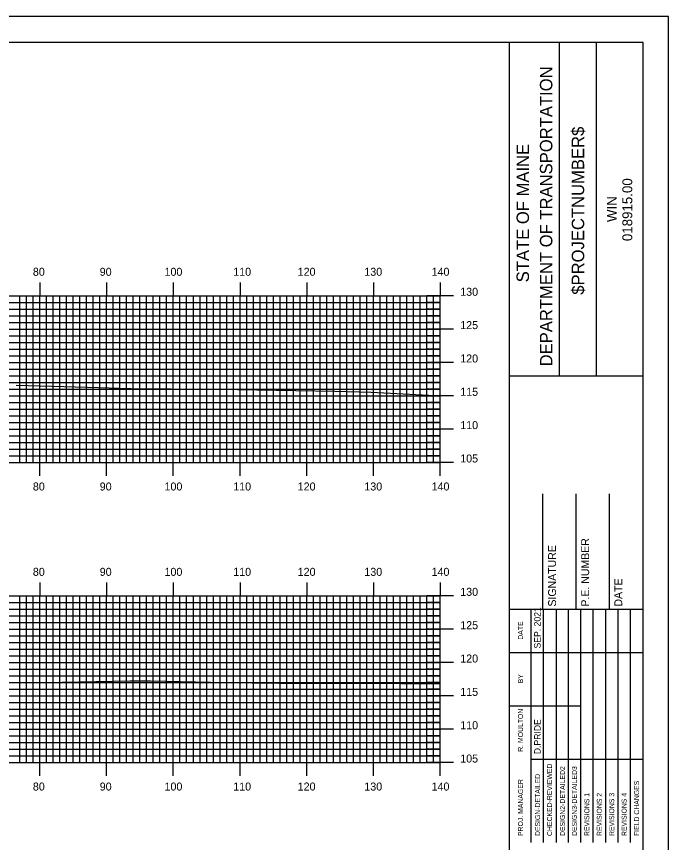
# Model space of a CAD drawing. Extents: x 844143 to 844486, y 363538 to 363758.
# Drawn here: x 844385 to 844482.7, y 363633.7 to 363757.6 of the extents above; entities that cross this region are included whole.
import ezdxf

# ---------------------------------------------------------------- set-up
doc = ezdxf.new("R2010")
doc.units = 0
for name, color, linetype in [('BORDER', 7, 'Continuous'), ('H_V ANNOTATION', 7, 'Continuous'), ('MAJOR', 7, 'Continuous'), ('MINOR', 7, 'Continuous'), ('PLOT BOUNDARY', 7, 'Continuous'), ('S_Roadway_Centerline', 7, 'Continuous')]:
    doc.layers.add(name, color=color, linetype=linetype)

msp = doc.modelspace()

# ---------------------------------------------------------------- linework, layer by layer
at = {"layer": 'BORDER'}
for p, q in [((844458.85, 363543.72), (844458.85, 363753.72)), ((844466.31, 363703.72), (844466.31, 363753.72)), ((844471.9, 363703.72), (844471.9, 363753.72)), ((844458.85, 363703.71), (844478.85, 363703.71)), ((844463.85, 363668.73), (844463.85, 363686.02)), ((844468.85, 363668.73), (844468.85, 363686.02)), ((844473.85, 363668.73), (844473.85, 363686.02)), ((844458.85, 363668.73), (844478.85, 363668.73))]:
    msp.add_line(p, q, dxfattribs=at)
msp.add_lwpolyline([(844158.85, 363543.72), (844478.85, 363543.72), (844478.85, 363753.72), (844158.85, 363753.72)], close=True, dxfattribs=at)
for points in [[(844462.08, 363662.23), (844462.08, 363668.73)], [(844463.95, 363633.73), (844463.95, 363668.73)], [(844465.81, 363668.73), (844465.81, 363633.73)], [(844467.67, 363633.73), (844467.67, 363668.73)], [(844469.54, 363633.73), (844469.54, 363668.73)], [(844471.4, 363633.73), (844471.4, 363668.73)], [(844473.26, 363633.73), (844473.26, 363668.73)], [(844475.13, 363633.73), (844475.13, 363668.73)], [(844476.99, 363633.73), (844476.99, 363668.73)], [(844462.08, 363633.73), (844462.08, 363667.31)], [(844458.85, 363662.23), (844478.85, 363662.23)], [(844458.85, 363654.23), (844462.08, 363654.23)], [(844462.08, 363654.23), (844469.53, 363654.23)], [(844462.08, 363646.23), (844478.85, 363646.23)]]:
    msp.add_lwpolyline(points, dxfattribs=at)
at = {"layer": 'MAJOR'}
for p, q in [((844388.45, 363717.73), (844388.45, 363715.72)), ((844398.45, 363717.73), (844398.45, 363715.72)), ((844408.45, 363717.73), (844408.45, 363715.72)), ((844418.45, 363717.73), (844418.45, 363715.72)), ((844428.45, 363717.73), (844428.45, 363715.72)), ((844438.45, 363717.73), (844438.45, 363715.72)), ((844448.45, 363717.73), (844448.45, 363715.72)), ((844168.45, 363715.72), (844448.45, 363715.72)), ((844168.45, 363715.72), (844448.45, 363715.72)), ((844388.45, 363690.72), (844388.45, 363715.72)), ((844398.45, 363690.72), (844398.45, 363715.72)), ((844408.45, 363690.72), (844408.45, 363715.72)), ((844418.45, 363690.72), (844418.45, 363715.72)), ((844428.45, 363690.72), (844428.45, 363715.72)), ((844438.45, 363690.72), (844438.45, 363715.72)), ((844450.45, 363715.72), (844446.45, 363715.72)), ((844448.45, 363690.72), (844448.45, 363715.72)), ((844448.45, 363690.72), (844448.45, 363715.72)), ((844168.45, 363710.72), (844448.45, 363710.72)), ((844450.45, 363710.72), (844446.45, 363710.72)), ((844168.45, 363705.72), (844448.45, 363705.72)), ((844450.45, 363705.72), (844446.45, 363705.72)), ((844168.45, 363700.72), (844448.45, 363700.72)), ((844450.45, 363700.72), (844446.45, 363700.72)), ((844168.45, 363695.72), (844448.45, 363695.72)), ((844450.45, 363695.72), (844446.45, 363695.72)), ((844168.45, 363690.72), (844448.45, 363690.72)), ((844168.45, 363690.72), (844448.45, 363690.72)), ((844388.45, 363688.72), (844388.45, 363690.72)), ((844398.45, 363688.72), (844398.45, 363690.72)), ((844408.45, 363688.72), (844408.45, 363690.72)), ((844418.45, 363688.72), (844418.45, 363690.72)), ((844428.45, 363688.72), (844428.45, 363690.72)), ((844438.45, 363688.72), (844438.45, 363690.72)), ((844450.45, 363690.72), (844446.45, 363690.72)), ((844448.45, 363688.72), (844448.45, 363690.72)), ((844388.45, 363672.73), (844388.45, 363670.72)), ((844398.45, 363672.73), (844398.45, 363670.72)), ((844408.45, 363672.73), (844408.45, 363670.72)), ((844418.45, 363672.73), (844418.45, 363670.72)), ((844428.45, 363672.73), (844428.45, 363670.72)), ((844438.45, 363672.73), (844438.45, 363670.72)), ((844448.45, 363672.73), (844448.45, 363670.72)), ((844168.45, 363670.72), (844448.45, 363670.72)), ((844168.45, 363670.72), (844448.45, 363670.72)), ((844388.45, 363645.72), (844388.45, 363670.72)), ((844398.45, 363645.72), (844398.45, 363670.72)), ((844408.45, 363645.72), (844408.45, 363670.72)), ((844418.45, 363645.72), (844418.45, 363670.72)), ((844428.45, 363645.72), (844428.45, 363670.72)), ((844438.45, 363645.72), (844438.45, 363670.72)), ((844450.45, 363670.72), (844446.45, 363670.72)), ((844448.45, 363645.72), (844448.45, 363670.72)), ((844448.45, 363645.72), (844448.45, 363670.72)), ((844168.45, 363665.72), (844448.45, 363665.72)), ((844450.45, 363665.72), (844446.45, 363665.72)), ((844168.45, 363660.72), (844448.45, 363660.72)), ((844450.45, 363660.72), (844446.45, 363660.72)), ((844168.45, 363655.72), (844448.45, 363655.72)), ((844450.45, 363655.72), (844446.45, 363655.72)), ((844168.45, 363650.72), (844448.45, 363650.72)), ((844450.45, 363650.72), (844446.45, 363650.72)), ((844168.45, 363645.72), (844448.45, 363645.72)), ((844168.45, 363645.72), (844448.45, 363645.72)), ((844388.45, 363643.72), (844388.45, 363645.72)), ((844398.45, 363643.72), (844398.45, 363645.72)), ((844408.45, 363643.72), (844408.45, 363645.72)), ((844418.45, 363643.72), (844418.45, 363645.72)), ((844428.45, 363643.72), (844428.45, 363645.72)), ((844438.45, 363643.72), (844438.45, 363645.72)), ((844450.45, 363645.72), (844446.45, 363645.72)), ((844448.45, 363643.72), (844448.45, 363645.72))]:
    msp.add_line(p, q, dxfattribs=at)
at = {"layer": 'MINOR'}
for p, q in [((844385.45, 363690.72), (844385.45, 363715.72)), ((844386.45, 363690.72), (844386.45, 363715.72)), ((844387.45, 363690.72), (844387.45, 363715.72)), ((844389.45, 363690.72), (844389.45, 363715.72)), ((844390.45, 363690.72), (844390.45, 363715.72)), ((844391.45, 363690.72), (844391.45, 363715.72)), ((844392.45, 363690.72), (844392.45, 363715.72)), ((844393.45, 363690.72), (844393.45, 363715.72)), ((844394.45, 363690.72), (844394.45, 363715.72)), ((844395.45, 363690.72), (844395.45, 363715.72)), ((844396.45, 363690.72), (844396.45, 363715.72)), ((844397.45, 363690.72), (844397.45, 363715.72)), ((844399.45, 363690.72), (844399.45, 363715.72)), ((844400.45, 363690.72), (844400.45, 363715.72)), ((844401.45, 363690.72), (844401.45, 363715.72)), ((844402.45, 363690.72), (844402.45, 363715.72)), ((844403.45, 363690.72), (844403.45, 363715.72)), ((844404.45, 363690.72), (844404.45, 363715.72)), ((844405.45, 363690.72), (844405.45, 363715.72)), ((844406.45, 363690.72), (844406.45, 363715.72)), ((844407.45, 363690.72), (844407.45, 363715.72)), ((844409.45, 363690.72), (844409.45, 363715.72)), ((844410.45, 363690.72), (844410.45, 363715.72)), ((844411.45, 363690.72), (844411.45, 363715.72)), ((844412.45, 363690.72), (844412.45, 363715.72)), ((844413.45, 363690.72), (844413.45, 363715.72)), ((844414.45, 363690.72), (844414.45, 363715.72)), ((844415.45, 363690.72), (844415.45, 363715.72)), ((844416.45, 363690.72), (844416.45, 363715.72)), ((844417.45, 363690.72), (844417.45, 363715.72)), ((844419.45, 363690.72), (844419.45, 363715.72)), ((844420.45, 363690.72), (844420.45, 363715.72)), ((844421.45, 363690.72), (844421.45, 363715.72)), ((844422.45, 363690.72), (844422.45, 363715.72)), ((844423.45, 363690.72), (844423.45, 363715.72)), ((844424.45, 363690.72), (844424.45, 363715.72)), ((844425.45, 363690.72), (844425.45, 363715.72)), ((844426.45, 363690.72), (844426.45, 363715.72)), ((844427.45, 363690.72), (844427.45, 363715.72)), ((844429.45, 363690.72), (844429.45, 363715.72)), ((844430.45, 363690.72), (844430.45, 363715.72)), ((844431.45, 363690.72), (844431.45, 363715.72)), ((844432.45, 363690.72), (844432.45, 363715.72)), ((844433.45, 363690.72), (844433.45, 363715.72)), ((844434.45, 363690.72), (844434.45, 363715.72)), ((844435.45, 363690.72), (844435.45, 363715.72)), ((844436.45, 363690.72), (844436.45, 363715.72)), ((844437.45, 363690.72), (844437.45, 363715.72)), ((844439.45, 363690.72), (844439.45, 363715.72)), ((844440.45, 363690.72), (844440.45, 363715.72)), ((844441.45, 363690.72), (844441.45, 363715.72)), ((844442.45, 363690.72), (844442.45, 363715.72)), ((844443.45, 363690.72), (844443.45, 363715.72)), ((844444.45, 363690.72), (844444.45, 363715.72)), ((844445.45, 363690.72), (844445.45, 363715.72)), ((844446.45, 363690.72), (844446.45, 363715.72)), ((844447.45, 363690.72), (844447.45, 363715.72)), ((844168.45, 363714.72), (844448.45, 363714.72)), ((844448.45, 363714.72), (844446.45, 363714.72)), ((844168.45, 363713.72), (844448.45, 363713.72)), ((844448.45, 363713.72), (844446.45, 363713.72)), ((844168.45, 363712.72), (844448.45, 363712.72)), ((844168.45, 363711.72), (844448.45, 363711.72)), ((844448.45, 363712.72), (844446.45, 363712.72)), ((844448.45, 363711.72), (844446.45, 363711.72)), ((844168.45, 363709.72), (844448.45, 363709.72)), ((844448.45, 363709.72), (844446.45, 363709.72)), ((844168.45, 363708.72), (844448.45, 363708.72)), ((844448.45, 363708.72), (844446.45, 363708.72)), ((844168.45, 363707.72), (844448.45, 363707.72)), ((844168.45, 363706.72), (844448.45, 363706.72)), ((844448.45, 363707.72), (844446.45, 363707.72)), ((844448.45, 363706.72), (844446.45, 363706.72)), ((844168.45, 363704.72), (844448.45, 363704.72)), ((844448.45, 363704.72), (844446.45, 363704.72)), ((844168.45, 363703.72), (844448.45, 363703.72)), ((844448.45, 363703.72), (844446.45, 363703.72)), ((844168.45, 363702.72), (844448.45, 363702.72)), ((844448.45, 363702.72), (844446.45, 363702.72)), ((844168.45, 363701.72), (844448.45, 363701.72)), ((844448.45, 363701.72), (844446.45, 363701.72)), ((844168.45, 363699.72), (844448.45, 363699.72)), ((844448.45, 363699.72), (844446.45, 363699.72)), ((844168.45, 363698.72), (844448.45, 363698.72)), ((844448.45, 363698.72), (844446.45, 363698.72)), ((844168.45, 363697.72), (844448.45, 363697.72)), ((844448.45, 363697.72), (844446.45, 363697.72)), ((844168.45, 363696.72), (844448.45, 363696.72)), ((844448.45, 363696.72), (844446.45, 363696.72)), ((844168.45, 363694.72), (844448.45, 363694.72)), ((844448.45, 363694.72), (844446.45, 363694.72)), ((844168.45, 363693.72), (844448.45, 363693.72)), ((844448.45, 363693.72), (844446.45, 363693.72)), ((844168.45, 363692.72), (844448.45, 363692.72)), ((844448.45, 363692.72), (844446.45, 363692.72)), ((844168.45, 363691.72), (844448.45, 363691.72)), ((844448.45, 363691.72), (844446.45, 363691.72)), ((844168.45, 363669.72), (844448.45, 363669.72)), ((844385.45, 363645.72), (844385.45, 363670.72)), ((844386.45, 363645.72), (844386.45, 363670.72)), ((844387.45, 363645.72), (844387.45, 363670.72)), ((844389.45, 363645.72), (844389.45, 363670.72)), ((844390.45, 363645.72), (844390.45, 363670.72)), ((844391.45, 363645.72), (844391.45, 363670.72)), ((844392.45, 363645.72), (844392.45, 363670.72)), ((844393.45, 363645.72), (844393.45, 363670.72)), ((844394.45, 363645.72), (844394.45, 363670.72)), ((844395.45, 363645.72), (844395.45, 363670.72)), ((844396.45, 363645.72), (844396.45, 363670.72)), ((844397.45, 363645.72), (844397.45, 363670.72)), ((844399.45, 363645.72), (844399.45, 363670.72)), ((844400.45, 363645.72), (844400.45, 363670.72)), ((844401.45, 363645.72), (844401.45, 363670.72)), ((844402.45, 363645.72), (844402.45, 363670.72)), ((844403.45, 363645.72), (844403.45, 363670.72)), ((844404.45, 363645.72), (844404.45, 363670.72)), ((844405.45, 363645.72), (844405.45, 363670.72)), ((844406.45, 363645.72), (844406.45, 363670.72)), ((844407.45, 363645.72), (844407.45, 363670.72)), ((844409.45, 363645.72), (844409.45, 363670.72)), ((844410.45, 363645.72), (844410.45, 363670.72)), ((844411.45, 363645.72), (844411.45, 363670.72)), ((844412.45, 363645.72), (844412.45, 363670.72)), ((844413.45, 363645.72), (844413.45, 363670.72)), ((844414.45, 363645.72), (844414.45, 363670.72)), ((844415.45, 363645.72), (844415.45, 363670.72)), ((844416.45, 363645.72), (844416.45, 363670.72)), ((844417.45, 363645.72), (844417.45, 363670.72)), ((844419.45, 363645.72), (844419.45, 363670.72)), ((844420.45, 363645.72), (844420.45, 363670.72)), ((844421.45, 363645.72), (844421.45, 363670.72)), ((844422.45, 363645.72), (844422.45, 363670.72)), ((844423.45, 363645.72), (844423.45, 363670.72)), ((844424.45, 363645.72), (844424.45, 363670.72)), ((844425.45, 363645.72), (844425.45, 363670.72)), ((844426.45, 363645.72), (844426.45, 363670.72)), ((844427.45, 363645.72), (844427.45, 363670.72)), ((844429.45, 363645.72), (844429.45, 363670.72)), ((844430.45, 363645.72), (844430.45, 363670.72)), ((844431.45, 363645.72), (844431.45, 363670.72)), ((844432.45, 363645.72), (844432.45, 363670.72)), ((844433.45, 363645.72), (844433.45, 363670.72)), ((844434.45, 363645.72), (844434.45, 363670.72)), ((844435.45, 363645.72), (844435.45, 363670.72)), ((844436.45, 363645.72), (844436.45, 363670.72)), ((844437.45, 363645.72), (844437.45, 363670.72)), ((844439.45, 363645.72), (844439.45, 363670.72)), ((844440.45, 363645.72), (844440.45, 363670.72)), ((844441.45, 363645.72), (844441.45, 363670.72)), ((844442.45, 363645.72), (844442.45, 363670.72)), ((844443.45, 363645.72), (844443.45, 363670.72)), ((844444.45, 363645.72), (844444.45, 363670.72)), ((844445.45, 363645.72), (844445.45, 363670.72)), ((844446.45, 363645.72), (844446.45, 363670.72)), ((844448.45, 363669.72), (844446.45, 363669.72)), ((844447.45, 363645.72), (844447.45, 363670.72)), ((844168.45, 363668.72), (844448.45, 363668.72)), ((844448.45, 363668.72), (844446.45, 363668.72)), ((844168.45, 363667.72), (844448.45, 363667.72)), ((844448.45, 363667.72), (844446.45, 363667.72)), ((844168.45, 363666.72), (844448.45, 363666.72)), ((844448.45, 363666.72), (844446.45, 363666.72)), ((844168.45, 363664.72), (844448.45, 363664.72)), ((844448.45, 363664.72), (844446.45, 363664.72)), ((844168.45, 363663.72), (844448.45, 363663.72)), ((844448.45, 363663.72), (844446.45, 363663.72)), ((844168.45, 363662.72), (844448.45, 363662.72)), ((844448.45, 363662.72), (844446.45, 363662.72)), ((844168.45, 363661.72), (844448.45, 363661.72)), ((844448.45, 363661.72), (844446.45, 363661.72)), ((844168.45, 363659.72), (844448.45, 363659.72)), ((844448.45, 363659.72), (844446.45, 363659.72)), ((844168.45, 363658.72), (844448.45, 363658.72)), ((844448.45, 363658.72), (844446.45, 363658.72)), ((844168.45, 363657.72), (844448.45, 363657.72)), ((844448.45, 363657.72), (844446.45, 363657.72)), ((844168.45, 363656.72), (844448.45, 363656.72)), ((844448.45, 363656.72), (844446.45, 363656.72)), ((844168.45, 363654.72), (844448.45, 363654.72)), ((844448.45, 363654.72), (844446.45, 363654.72)), ((844168.45, 363653.72), (844448.45, 363653.72)), ((844448.45, 363653.72), (844446.45, 363653.72)), ((844168.45, 363652.72), (844448.45, 363652.72)), ((844448.45, 363652.72), (844446.45, 363652.72)), ((844168.45, 363651.72), (844448.45, 363651.72)), ((844448.45, 363651.72), (844446.45, 363651.72)), ((844168.45, 363649.72), (844448.45, 363649.72)), ((844448.45, 363649.72), (844446.45, 363649.72)), ((844168.45, 363648.72), (844448.45, 363648.72)), ((844448.45, 363648.72), (844446.45, 363648.72)), ((844168.45, 363647.72), (844448.45, 363647.72)), ((844448.45, 363647.72), (844446.45, 363647.72)), ((844168.45, 363646.72), (844448.45, 363646.72)), ((844448.45, 363646.72), (844446.45, 363646.72))]:
    msp.add_line(p, q, dxfattribs=at)
at = {"layer": 'PLOT BOUNDARY'}
msp.add_lwpolyline([(844142.66, 363537.6), (844482.66, 363537.6), (844482.66, 363757.6), (844142.66, 363757.6)], close=True, dxfattribs=at)
at = {"layer": 'S_Roadway_Centerline'}
for points in [[(844384.9, 363702.32), (844395.61, 363702.04), (844402.07, 363701.84), (844414.21, 363701.74), (844415.13, 363701.71), (844432.67, 363701.42), (844438.12, 363701.27), (844447.7, 363700.78), (844448.45, 363700.72)], [(844379.75, 363657.74), (844386.66, 363657.73), (844391.74, 363657.79), (844401.94, 363657.97), (844403.95, 363657.98), (844405.05, 363657.95), (844416.29, 363657.72), (844424.28, 363657.6), (844435.36, 363657.63), (844440.1, 363657.6), (844442.66, 363657.59), (844448.45, 363657.55)]]:
    msp.add_lwpolyline(points, dxfattribs=at)

# ---------------------------------------------------------------- texts
at = {"layer": 'BORDER'}
for s, height, p in [('DEPARTMENT OF TRANSPORTATION', 1.8635, (844465.26, 363705.13)), ('$PROJECTNUMBER$', 1.8635, (844470.03, 363715.88)), ('STATE OF MAINE', 1.8635, (844461.76, 363717.74)), ('018915.00', 1.491, (844477.24, 363723.92)), ('WIN', 1.491, (844474.92, 363726.78)), ('SIGNATURE', 1.181, (844465.81, 363669.11)), ('P.E. NUMBER', 1.1811, (844470.77, 363669.11)), ('DATE', 1.181, (844475.73, 363669.11)), ('SEP. 2021', 0.969, (844463.5, 363662.82)), ('DATE', 0.743, (844460.86, 363664.14)), ('BY', 0.743, (844460.86, 363657.6)), ('R. MOULTON', 0.745, (844460.86, 363647.33)), ('D.PRIDE', 0.969, (844463.5, 363646.97)), ('CHECKED-REVIEWED', 0.7455, (844465.21, 363634.7)), ('DESIGN2-DETAILED2', 0.7455, (844467.15, 363634.7)), ('DESIGN3-DETAILED3', 0.7455, (844468.94, 363634.7)), ('DESIGN-DETAILED', 0.7455, (844463.42, 363634.7)), ('PROJ. MANAGER', 0.7455, (844460.86, 363634.7)), ('FIELD CHANGES', 0.7455, (844478.26, 363634.7)), ('REVISIONS 1', 0.7455, (844470.8, 363634.7)), ('REVISIONS 2', 0.7455, (844472.67, 363634.7)), ('REVISIONS 3', 0.7455, (844474.53, 363634.7)), ('REVISIONS 4', 0.7455, (844476.39, 363634.7))]:
    msp.add_text(s, height=height, rotation=90, dxfattribs=at).set_placement(p)
at = {"layer": 'H_V ANNOTATION'}
for s, p in [('80', (844387.4, 363718.72)), ('90', (844397.42, 363718.72)), ('100', (844407.13, 363718.72)), ('110', (844417.43, 363718.72)), ('120', (844427.09, 363718.72)), ('130', (844437.08, 363718.72)), ('140', (844447.16, 363718.72)), ('130', (844451.45, 363715.72)), ('125', (844451.45, 363710.72)), ('120', (844451.45, 363705.72)), ('115', (844451.45, 363700.72)), ('110', (844451.45, 363695.72)), ('105', (844451.45, 363690.72)), ('80', (844387.4, 363686.52)), ('90', (844397.42, 363686.52)), ('100', (844407.13, 363686.52)), ('110', (844417.43, 363686.52)), ('120', (844427.09, 363686.52)), ('130', (844437.08, 363686.52)), ('140', (844447.16, 363686.52)), ('80', (844387.4, 363673.72)), ('90', (844397.42, 363673.72)), ('100', (844407.13, 363673.72)), ('110', (844417.43, 363673.72)), ('120', (844427.09, 363673.72)), ('130', (844437.08, 363673.72)), ('140', (844447.16, 363673.72)), ('130', (844451.45, 363670.72)), ('125', (844451.45, 363665.72)), ('120', (844451.45, 363660.72)), ('115', (844451.45, 363655.72)), ('110', (844451.45, 363650.72)), ('105', (844451.45, 363645.72)), ('80', (844387.4, 363641.52)), ('90', (844397.42, 363641.52)), ('100', (844407.13, 363641.52)), ('110', (844417.43, 363641.52)), ('120', (844427.09, 363641.52)), ('130', (844437.08, 363641.52)), ('140', (844447.16, 363641.52))]:
    msp.add_text(s, height=1.2, dxfattribs=at).set_placement(p)

doc.saveas('drawing.dxf')
